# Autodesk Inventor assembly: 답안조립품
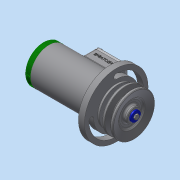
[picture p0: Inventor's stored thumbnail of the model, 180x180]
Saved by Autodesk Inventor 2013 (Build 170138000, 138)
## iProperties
Created: 2017-05
Part Number: 답안조립품
Document SubType Name: Weldment
Designer: dgall
Weld Material: Welded Aluminum-6061
Author: dgall
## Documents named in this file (20)
- C:\Users\dgall\Desktop\470507V1014\OldVersions\답안조립품.iam
- C:\Users\dgall\Desktop\470507V1014\1. 본체.ipt
- C:\Users\dgall\Desktop\470507V1014\V-벨트풀리.ipt
- C:\Users\dgall\Desktop\470507V1014\너트 M10.ipt
- C:\Users\dgall\Desktop\470507V1014\멈춤링 15 x 1.ipt
- C:\Users\dgall\Desktop\470507V1014\멈춤링 35x1.6.ipt
- C:\Users\dgall\Desktop\470507V1014\볼트 M4 x 10.ipt
- C:\Users\dgall\Desktop\470507V1014\부시2.ipt
- C:\Users\dgall\Desktop\470507V1014\사이드 커버.ipt
- 사이드 커버.ipt
- C:\Users\dgall\Desktop\470507V1014\오일 실 15 25 7.ipt
- C:\Users\dgall\Desktop\470507V1014\와셔 4x16.ipt
- C:\Users\dgall\Desktop\470507V1014\와셔 10x21.ipt
- C:\Users\dgall\Desktop\470507V1014\축.ipt
- C:\Users\dgall\Desktop\470507V1014\키 4 x 4 x 18.ipt
- C:\Users\dgall\Desktop\470507V1014\탑 커버.ipt
- C:\Users\dgall\Desktop\470507V1014\부시1.ipt
- C:\Users\dgall\Desktop\470507V1014\베어링 15 x 35 x 11.ipt
- C:\Users\dgall\Desktop\470507V1014\십자볼트 M3 x 10.ipt
- C:\Users\dgall\Desktop\470507V1014\와셔 3x6.ipt
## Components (3 placed, 3 different names)
1. 1. 본체:1
2. V-벨트풀리:1
3. ISO 4017 M4 x 10:1
